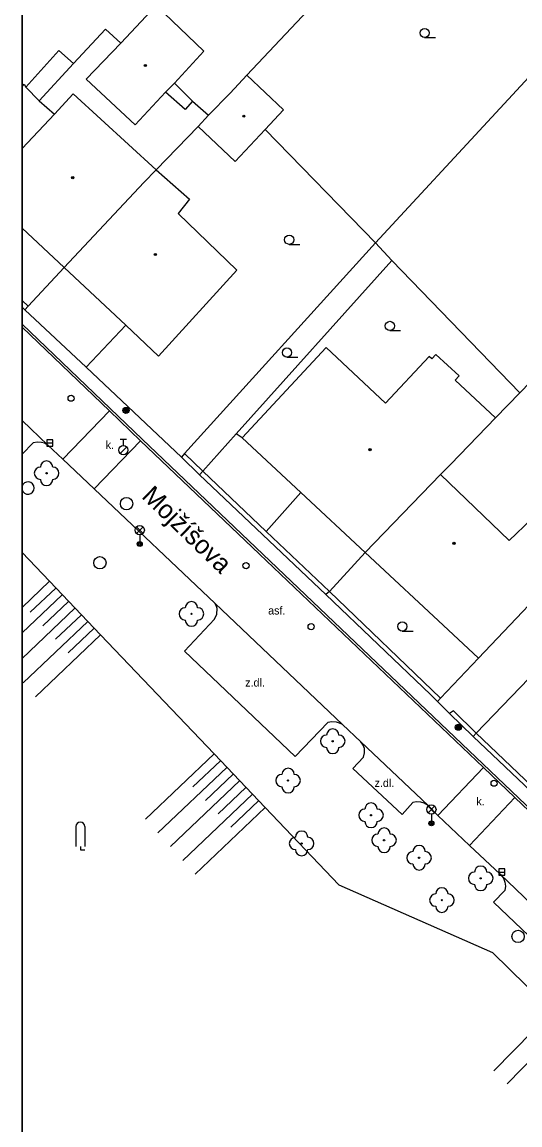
# Model space of a CAD drawing. Extents: x -598233 to -596890, y -1157848 to -1156431.
# Drawn here: x -598232.9 to -598192.5, y -1157074.8 to -1156985.2 of the extents above; entities that cross this region are included whole.
import ezdxf

# ---------------------------------------------------------------- set-up
doc = ezdxf.new("R2010")
doc.units = 0
for name, color, linetype in [('Level 10', 7, 'Continuous'), ('Level 11', 7, 'Continuous'), ('Level 14', 7, 'Continuous'), ('Level 15', 7, 'Continuous'), ('Level 22', 7, 'Continuous'), ('Level 25', 7, 'Continuous'), ('Level 27', 7, 'Continuous'), ('Level 28', 7, 'Continuous'), ('Level 33', 7, 'Continuous'), ('Level 36', 7, 'Continuous'), ('Level 39', 7, 'Continuous'), ('Level 40', 7, 'Continuous'), ('Level 49', 7, 'Continuous'), ('Level 5', 7, 'Continuous'), ('Level 7', 7, 'Continuous'), ('Level 8', 7, 'Continuous'), ('Vrstva 27', 7, 'Continuous'), ('Vrstva 60', 7, 'Continuous'), ('zajmove_uzemi', 7, 'Continuous')]:
    doc.layers.add(name, color=color, linetype=linetype)

msp = doc.modelspace()

# ---------------------------------------------------------------- linework, layer by layer
at = {"layer": 'Level 10'}
for p, q in [((-598225.8, -1157016.77), (-598232.8901, -1157009.9954)), ((-598232.8901, -1157017.5685), (-598230.79, -1157019.56))]:
    msp.add_line(p, q, dxfattribs=at)
for points in [[(-598223.29, -1157019.21), (-598225.8, -1157016.77)], [(-598230.79, -1157019.56), (-598229.57, -1157020.71)], [(-598195.43, -1157045.75), (-598223.29, -1157019.21)], [(-598229.57, -1157020.71), (-598227.04, -1157023.11)], [(-598227.04, -1157023.11), (-598217.21, -1157032.43)], [(-598217.21, -1157032.43), (-598206.88, -1157042.25)], [(-598206.88, -1157042.25), (-598205.39, -1157043.67)], [(-598205.39, -1157043.67), (-598199.93, -1157048.84)], [(-598192.89, -1157048.17), (-598195.43, -1157045.75)], [(-598162.11, -1157077.54), (-598192.89, -1157048.17)], [(-598199.93, -1157048.84), (-598199.14, -1157049.63)], [(-598199.14, -1157049.63), (-598196.57, -1157052.07)], [(-598196.57, -1157052.07), (-598194.1, -1157054.39)], [(-598194.1, -1157054.39), (-598184.5, -1157063.57)]]:
    msp.add_lwpolyline(points, dxfattribs=at)
at = {"layer": 'Level 11'}
for points in [[(-598196.2199, -1156969.9699), (-598214.6599, -1156989.54)], [(-598184.68, -1156981.99), (-598204.21, -1157003.13)], [(-598228.7199, -1156988.58), (-598226.12, -1156985.79)], [(-598226.12, -1156985.79), (-598224.87, -1156986.94)], [(-598232.58, -1156990.49), (-598229.9099, -1156987.53)], [(-598229.9099, -1156987.53), (-598228.7199, -1156988.58)], [(-598228.7199, -1156988.58), (-598231.5, -1156991.62)], [(-598220.52, -1156990.18), (-598219.05, -1156991.64)], [(-598219.05, -1156991.64), (-598219.65, -1156992.32), (-598221.25, -1156990.9)], [(-598219.05, -1156991.64), (-598217.77, -1156992.78)], [(-598218.61, -1156993.7), (-598222.02, -1156997.2199)], [(-598213.15, -1156993.93), (-598204.21, -1157003.13)], [(-598202.87, -1157004.57), (-598204.21, -1157003.13)], [(-598218.23, -1157021.67), (-598215.51, -1157018.64), (-598202.87, -1157004.57)], [(-598192.49, -1157015.32), (-598202.87, -1157004.57)], [(-598119.12, -1157118.36), (-598170.97, -1157068.86), (-598181.78, -1157058.53), (-598183.88, -1157056.53), (-598183.95, -1157056.46), (-598223.15, -1157019.07), (-598232.8901, -1157009.7438)], [(-598224.4699, -1157009.83), (-598227.69, -1157013.25)], [(-598225.8, -1157016.77), (-598229.57, -1157020.71)], [(-598215.03, -1157018.97), (-598215.51, -1157018.64)], [(-598230.79, -1157019.56), (-598231.07, -1157019.42), (-598231.31, -1157019.34), (-598231.63, -1157019.32), (-598232, -1157019.38), (-598232.8901, -1157020.3113)], [(-598223.29, -1157019.21), (-598227.04, -1157023.11)], [(-598218.49, -1157021.9699), (-598218.23, -1157021.67)], [(-598210.26, -1157023.42), (-598213.08, -1157026.57)], [(-598206.88, -1157042.25), (-598207.13, -1157042.13), (-598207.38, -1157042.05), (-598207.75, -1157042.03), (-598208.07, -1157042.1), (-598210.7199, -1157044.84), (-598219.7199, -1157036.3), (-598217.27, -1157033.71), (-598217.09, -1157033.29), (-598217.07, -1157032.84), (-598217.1, -1157032.68), (-598217.21, -1157032.43)], [(-598195.85, -1157036.86), (-598198.94, -1157040.11)], [(-598199.93, -1157048.84), (-598200.25, -1157048.63), (-598200.53, -1157048.55), (-598200.87, -1157048.52), (-598201.19, -1157048.58), (-598202.03, -1157049.57), (-598206.04, -1157045.82), (-598205.18, -1157044.89), (-598205.09, -1157044.54), (-598205.11, -1157044.21), (-598205.2199, -1157043.92), (-598205.39, -1157043.67)], [(-598195.43, -1157045.75), (-598199.14, -1157049.63)], [(-598192.89, -1157048.17), (-598196.57, -1157052.07)], [(-598194.1, -1157054.39), (-598193.83, -1157054.7199), (-598193.7, -1157055.05), (-598193.6599, -1157055.37), (-598193.71, -1157055.7199), (-598194.62, -1157056.68), (-598186.6599, -1157064.27), (-598185.71, -1157063.34), (-598185.38, -1157063.28), (-598185.05, -1157063.32), (-598184.78, -1157063.4), (-598184.5, -1157063.57)]]:
    msp.add_lwpolyline(points, dxfattribs=at)
at = {"layer": 'Level 14'}
msp.add_lwpolyline([(-598232.8901, -1157028.2912), (-598230.67, -1157030.62), (-598226.53, -1157034.9699), (-598217.31, -1157044.64), (-598213.17, -1157048.99), (-598207.18, -1157055.27), (-598194.7, -1157060.77), (-598176.86, -1157078.27), (-598172.4699, -1157082.89), (-598166.27, -1157089.42), (-598160.4699, -1157095.53)], dxfattribs=at)
at = {"layer": 'Level 15'}
for p, q in [((-598230.67, -1157030.62), (-598232.8901, -1157032.7409)), ((-598229.63, -1157031.71), (-598232.8901, -1157034.813)), ((-598228.6, -1157032.8), (-598232.8901, -1157036.8846))]:
    msp.add_line(p, q, dxfattribs=at)
for points in [[(-598230.15, -1157031.17), (-598232.2199, -1157033.14)], [(-598229.12, -1157032.25), (-598231.2, -1157034.24)], [(-598228.08, -1157033.34), (-598230.17, -1157035.33)], [(-598227.56, -1157033.88), (-598232.81, -1157038.88)], [(-598226.53, -1157034.9699), (-598231.81, -1157040)], [(-598227.05, -1157034.42), (-598229.15, -1157036.43)], [(-598217.31, -1157044.64), (-598222.86, -1157049.94)], [(-598216.27, -1157045.73), (-598221.86, -1157051.05)], [(-598216.79, -1157045.19), (-598219.02, -1157047.31)], [(-598215.24, -1157046.82), (-598220.85, -1157052.17)], [(-598215.76, -1157046.27), (-598218, -1157048.4099)], [(-598214.7199, -1157047.36), (-598216.9699, -1157049.5)], [(-598214.2, -1157047.9), (-598219.85, -1157053.28)], [(-598213.69, -1157048.44), (-598215.95, -1157050.6)], [(-598213.17, -1157048.99), (-598218.84, -1157054.4)], [(-598189.85, -1157065.52), (-598194.6, -1157070.36)], [(-598188.78, -1157066.57), (-598193.53, -1157071.42)]]:
    msp.add_lwpolyline(points, dxfattribs=at)
at = {"layer": 'Level 22'}
for centre in [(-598230.9, -1157021.85), (-598219.14, -1157033.27), (-598207.68, -1157043.61), (-598211.3, -1157046.8), (-598204.57, -1157049.62), (-598210.2, -1157051.9099), (-598203.51, -1157051.65), (-598200.67, -1157053.07), (-598195.67, -1157054.74), (-598198.82, -1157056.51)]:
    msp.add_circle(centre, 0.05, dxfattribs=at)
for centre, start, end in [((-598230.9, -1157021.35), 0, 180), ((-598231.4, -1157021.85), 90, 270), ((-598230.4, -1157021.85), 270, 90), ((-598230.9, -1157022.35), 180, 0), ((-598219.14, -1157032.77), 0, 180), ((-598219.64, -1157033.27), 90, 270), ((-598218.64, -1157033.27), 270, 90), ((-598219.14, -1157033.77), 180, 0), ((-598208.18, -1157043.61), 90, 270), ((-598207.68, -1157043.11), 0, 180), ((-598207.18, -1157043.61), 270, 90), ((-598207.68, -1157044.11), 180, 0), ((-598211.3, -1157046.3), 0, 180), ((-598211.8, -1157046.8), 90, 270), ((-598210.8, -1157046.8), 270, 90), ((-598211.3, -1157047.3), 180, 0), ((-598204.57, -1157049.12), 0, 180), ((-598205.07, -1157049.62), 90, 270), ((-598204.07, -1157049.62), 270, 90), ((-598204.57, -1157050.12), 180, 0), ((-598210.2, -1157051.4099), 0, 180), ((-598204.01, -1157051.65), 90, 270), ((-598203.51, -1157051.15), 0, 180), ((-598203.01, -1157051.65), 270, 90), ((-598210.7, -1157051.9099), 90, 270), ((-598209.7, -1157051.9099), 270, 90), ((-598203.51, -1157052.15), 180, 0), ((-598200.67, -1157052.57), 0, 180), ((-598210.2, -1157052.4099), 180, 0), ((-598201.17, -1157053.07), 90, 270), ((-598200.17, -1157053.07), 270, 90), ((-598200.67, -1157053.57), 180, 0), ((-598195.67, -1157054.24), 0, 180), ((-598196.17, -1157054.74), 90, 270), ((-598195.17, -1157054.74), 270, 90), ((-598198.82, -1157056.01), 0, 180), ((-598195.67, -1157055.24), 180, 0), ((-598199.32, -1157056.51), 90, 270), ((-598198.32, -1157056.51), 270, 90), ((-598198.82, -1157057.01), 180, 0)]:
    msp.add_arc(centre, 0.5, start, end, dxfattribs=at)
at = {"layer": 'Level 25'}
for centre, radius in [((-598224.46, -1157016.75), 0.25), ((-598224.46, -1157016.75), 0.2), ((-598224.46, -1157016.75), 0.15), ((-598224.46, -1157016.75), 0.1), ((-598224.46, -1157016.75), 0.05), ((-598197.48, -1157042.4699), 0.25), ((-598197.48, -1157042.4699), 0.2), ((-598197.48, -1157042.4699), 0.15), ((-598197.48, -1157042.4699), 0.1), ((-598197.48, -1157042.4699), 0.05)]:
    msp.add_circle(centre, radius, dxfattribs=at)
at = {"layer": 'Level 27'}
for p, q in [((-598230.89, -1157019.39), (-598230.39, -1157019.39)), ((-598194.2, -1157054.23), (-598193.7, -1157054.23))]:
    msp.add_line(p, q, dxfattribs=at)
for points in [[(-598230.89, -1157019.64), (-598230.39, -1157019.64), (-598230.39, -1157019.14), (-598230.89, -1157019.14)], [(-598194.2, -1157054.48), (-598193.7, -1157054.48), (-598193.7, -1157053.98), (-598194.2, -1157053.98)]]:
    msp.add_lwpolyline(points, close=True, dxfattribs=at)
for centre in [(-598224.4099, -1157024.32), (-598226.57, -1157029.12), (-598192.64, -1157059.46)]:
    msp.add_circle(centre, 0.5, dxfattribs=at)
at = {"layer": 'Level 28'}
for p, q in [((-598224.92, -1157019.0949), (-598224.42, -1157019.0949)), ((-598224.67, -1157019.5949), (-598224.67, -1157019.0949)), ((-598224.928, -1157020.2419), (-598224.398, -1157019.7119))]:
    msp.add_line(p, q, dxfattribs=at)
for centre, radius in [((-598228.9099, -1157015.76), 0.25), ((-598224.67, -1157019.9699), 0.375), ((-598214.71, -1157029.36), 0.25), ((-598209.43, -1157034.31), 0.25), ((-598194.58, -1157047.02), 0.25)]:
    msp.add_circle(centre, radius, dxfattribs=at)
at = {"layer": 'Level 33'}
for p, q in [((-598223.605, -1157026.73), (-598223.075, -1157026.2)), ((-598223.605, -1157026.2), (-598223.075, -1157026.73)), ((-598223.34, -1157026.84), (-598223.34, -1157027.59)), ((-598199.935, -1157049.42), (-598199.405, -1157048.89)), ((-598199.935, -1157048.89), (-598199.405, -1157049.42)), ((-598199.67, -1157049.53), (-598199.67, -1157050.28))]:
    msp.add_line(p, q, dxfattribs=at)
for centre, radius in [((-598223.34, -1157026.465), 0.375), ((-598223.34, -1157027.59), 0.2), ((-598223.34, -1157027.59), 0.1445), ((-598223.34, -1157027.59), 0.0876), ((-598199.67, -1157049.155), 0.375), ((-598199.67, -1157050.28), 0.2), ((-598199.67, -1157050.28), 0.1445), ((-598199.67, -1157050.28), 0.0876)]:
    msp.add_circle(centre, radius, dxfattribs=at)
at = {"layer": 'Level 36'}
for p, q in [((-598200.2199, -1156986.475), (-598199.3449, -1156986.475)), ((-598211.21, -1157003.265), (-598210.335, -1157003.265)), ((-598203.04, -1157010.265), (-598202.165, -1157010.265)), ((-598211.39, -1157012.425), (-598210.515, -1157012.425)), ((-598202.03, -1157034.665), (-598201.155, -1157034.665)), ((-598228.5349, -1157050.545), (-598228.5349, -1157052.17)), ((-598227.7849, -1157050.545), (-598227.7849, -1157052.17))]:
    msp.add_line(p, q, dxfattribs=at)
msp.add_lwpolyline([(-598228.1599, -1157052.17), (-598228.1599, -1157052.42), (-598227.7849, -1157052.42)], dxfattribs=at)
for centre in [(-598200.22, -1156986.0999), (-598211.2101, -1157002.8899), (-598203.0401, -1157009.8899), (-598211.3901, -1157012.0499), (-598202.0301, -1157034.2899)]:
    msp.add_circle(centre, 0.375, dxfattribs=at)
msp.add_arc((-598228.1602, -1157050.5446), 0.375, 0, 180, dxfattribs=at)
at = {"layer": 'Level 39'}
for centre, radius in [((-598222.88, -1156988.74), 0.09), ((-598222.88, -1156988.74), 0.0398), ((-598214.89, -1156992.86), 0.09), ((-598214.89, -1156992.86), 0.0398), ((-598228.78, -1156997.85), 0.09), ((-598228.78, -1156997.85), 0.0398), ((-598222.07, -1157004.09), 0.09), ((-598222.07, -1157004.09), 0.0398), ((-598204.65, -1157019.94), 0.09), ((-598204.65, -1157019.94), 0.0398), ((-598197.84, -1157027.54), 0.09), ((-598197.84, -1157027.54), 0.0398)]:
    msp.add_circle(centre, radius, dxfattribs=at)
at = {"layer": 'Level 5'}
for p, q in [((-598232.8901, -1156990.4453), (-598232.73, -1156990.27)), ((-598232.8901, -1156995.4927), (-598230.25, -1156992.7)), ((-598229.46, -1157005.14), (-598232.8901, -1157001.9634))]:
    msp.add_line(p, q, dxfattribs=at)
for points in [[(-598224.87, -1156986.94), (-598222.01, -1156983.88)], [(-598222.01, -1156983.88), (-598218.13, -1156987.57)], [(-598227.69, -1156989.85), (-598224.87, -1156986.94)], [(-598218.13, -1156987.57), (-598220.52, -1156990.18)], [(-598216.01, -1156990.98), (-598214.6599, -1156989.54)], [(-598214.6599, -1156989.54), (-598211.67, -1156992.34)], [(-598232.73, -1156990.27), (-598232.58, -1156990.49)], [(-598223.71, -1156993.56), (-598227.69, -1156989.85)], [(-598220.52, -1156990.18), (-598221.25, -1156990.9)], [(-598231.5, -1156991.62), (-598232.58, -1156990.49)], [(-598230.25, -1156992.7), (-598228.73, -1156991.04)], [(-598228.73, -1156991.04), (-598222.02, -1156997.2199)], [(-598221.25, -1156990.9), (-598223.71, -1156993.56)], [(-598217.77, -1156992.78), (-598216.01, -1156990.98)], [(-598231.5, -1156991.62), (-598230.25, -1156992.7)], [(-598218.61, -1156993.7), (-598217.77, -1156992.78)], [(-598211.67, -1156992.34), (-598213.15, -1156993.93)], [(-598215.59, -1156996.53), (-598218.61, -1156993.7)], [(-598213.15, -1156993.93), (-598215.59, -1156996.53)], [(-598222.02, -1156997.2199), (-598223.02, -1156998.23)], [(-598222.02, -1156997.2199), (-598219.3, -1156999.59)], [(-598229.46, -1157005.14), (-598223.02, -1156998.23)], [(-598219.3, -1156999.59), (-598220.2199, -1157000.77)], [(-598220.2199, -1157000.77), (-598215.4699, -1157005.36)], [(-598224.4699, -1157009.83), (-598229.46, -1157005.14)], [(-598215.4699, -1157005.36), (-598221.81, -1157012.34)], [(-598221.81, -1157012.34), (-598224.4699, -1157009.83)], [(-598215.03, -1157018.9699), (-598208.21, -1157011.65)], [(-598208.21, -1157011.65), (-598203.39, -1157016.1599)], [(-598199.85, -1157012.36), (-598203.39, -1157016.1599)], [(-598199.63, -1157012.57), (-598199.85, -1157012.36)], [(-598199.31, -1157012.21), (-598199.63, -1157012.57)], [(-598197.43, -1157013.95), (-598199.31, -1157012.21)], [(-598197.75, -1157014.3), (-598197.43, -1157013.95)], [(-598194.46, -1157017.36), (-598197.75, -1157014.3)], [(-598191.63, -1157014.42), (-598192.49, -1157015.32)], [(-598192.49, -1157015.32), (-598194.46, -1157017.36)], [(-598194.46, -1157017.36), (-598198.09, -1157021.1)], [(-598205.05, -1157028.28), (-598210.26, -1157023.42), (-598215.03, -1157018.97)], [(-598198.09, -1157021.1), (-598198.93, -1157021.96)], [(-598198.93, -1157021.96), (-598205.05, -1157028.28)], [(-598198.93, -1157021.96), (-598193.36, -1157027.3)], [(-598193.36, -1157027.3), (-598191.54, -1157025.57), (-598190.65, -1157024.73)], [(-598198.31, -1157034.56), (-598205.05, -1157028.28)], [(-598188.19, -1157028.79), (-598195.85, -1157036.86)], [(-598195.85, -1157036.86), (-598198.31, -1157034.56)]]:
    msp.add_lwpolyline(points, dxfattribs=at)
at = {"layer": 'Level 7'}
for p, q in [((-598232.4, -1157008.29), (-598232.8901, -1157007.8318)), ((-598232.6599, -1157008.57), (-598232.8901, -1157008.3531))]:
    msp.add_line(p, q, dxfattribs=at)
for points in [[(-598204.21, -1157003.13), (-598219.7, -1157020.24)], [(-598229.46, -1157005.14), (-598232.4, -1157008.29)], [(-598232.4, -1157008.29), (-598232.6599, -1157008.57)], [(-598219.96, -1157020.54), (-598227.69, -1157013.25)], [(-598219.7, -1157020.24), (-598219.96, -1157020.54)], [(-598218.49, -1157021.9699), (-598219.96, -1157020.54)], [(-598219.7, -1157020.24), (-598218.23, -1157021.67)], [(-598218.23, -1157021.67), (-598213.08, -1157026.57), (-598207.95, -1157031.46)], [(-598208.25, -1157031.7), (-598218.49, -1157021.9699)], [(-598178.9, -1157025.17), (-598196.05, -1157042.96)], [(-598205.05, -1157028.28), (-598207.95, -1157031.46)], [(-598207.95, -1157031.46), (-598208.25, -1157031.7)], [(-598198.94, -1157040.11), (-598207.95, -1157031.46)], [(-598199.17, -1157040.39), (-598199.74, -1157039.82), (-598208.25, -1157031.7)], [(-598198.94, -1157040.11), (-598199.17, -1157040.39)], [(-598197.88, -1157041.14), (-598198.2, -1157041.35)], [(-598196.28, -1157043.23), (-598198.2, -1157041.35)], [(-598197.88, -1157041.14), (-598196.05, -1157042.96)], [(-598196.05, -1157042.96), (-598196.28, -1157043.23)], [(-598184.32, -1157054.57), (-598196.28, -1157043.23)], [(-598196.05, -1157042.96), (-598190.96, -1157047.81), (-598184.11, -1157054.32)]]:
    msp.add_lwpolyline(points, dxfattribs=at)
at = {"layer": 'Level 8'}
for points in [[(-598232.6599, -1157008.57), (-598227.69, -1157013.25)], [(-598199.17, -1157040.39), (-598198.2, -1157041.35)]]:
    msp.add_lwpolyline(points, dxfattribs=at)
at = {"layer": 'Vrstva 27'}
msp.add_line((-598232.8901, -1157022.9105), (-598232.8901, -1157023.1895), dxfattribs=at)
msp.add_arc((-598232.4099, -1157023.05), 0.5, 196.195662, 163.804338, dxfattribs=at)
at = {"layer": 'Vrstva 60'}
msp.add_lwpolyline([(-598232.8901, -1156430.8558), (-598232.8901, -1157835.5817), (-598232.81, -1157835.6), (-598231.24, -1157835.95), (-598223.73, -1157837.73), (-598218.75, -1157838.85), (-598190.54, -1157845.18), (-598175.89, -1157848.4611), (-598170.5079, -1157848.4611), (-598170.38, -1157848.22), (-598166.89, -1157841.65), (-598165.3, -1157838.66), (-598164.37, -1157836.9), (-598161.86, -1157832.18), (-598161.19, -1157830.95), (-598160.05, -1157828.86), (-598157.63, -1157824.55), (-598144.71, -1157839.14), (-598136.4065, -1157848.4611), (-597003.6644, -1157848.4611)], dxfattribs=at)
at = {"layer": 'zajmove_uzemi'}
msp.add_lwpolyline([(-598232.8901, -1156430.8558), (-596890.4624, -1156430.8558), (-596890.4624, -1157848.4611), (-598232.8901, -1157848.4611)], close=True, dxfattribs=at)

# ---------------------------------------------------------------- texts
at = {"layer": 'Level 40'}
for s, p in [('k. ', (-598226.1, -1157019.87)), ('asf.', (-598212.92, -1157033.32)), ('z.dl.', (-598214.78, -1157039.17)), ('z.dl.', (-598204.28, -1157047.32)), ('k. ', (-598196.02, -1157048.81))]:
    msp.add_text(s, height=0.65, dxfattribs=at).set_placement(p)
at = {"layer": 'Level 49'}
msp.add_text('Mojžíšova', height=1.5, rotation=316, dxfattribs=at).set_placement((-598223.26, -1157023.81))

doc.saveas('drawing.dxf')
